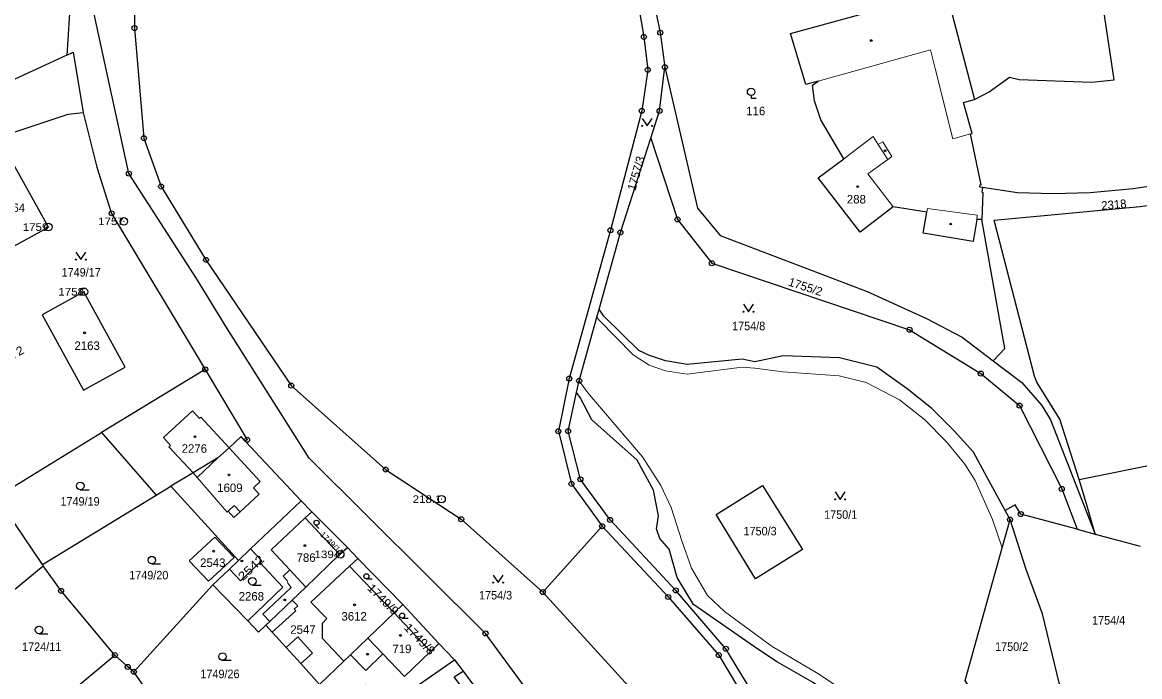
# Model space of a CAD drawing. Extents: x -679733 to -673243, y -1075091 to -1066557.
# Drawn here: x -676657.5 to -676434.7, y -1072048.7 to -1071918.1 of the extents above; entities that cross this region are included whole.
import ezdxf
from ezdxf.enums import TextEntityAlignment as Align

# ---------------------------------------------------------------- set-up
doc = ezdxf.new("R2010")
doc.units = 0
doc.header["$LTSCALE"] = 0.68
for name, color, linetype, lineweight in [('1', 7, 'Continuous', 25), ('3', 7, 'Continuous', 25), ('4', 7, 'Continuous', 13), ('5', 7, 'Continuous', 25), ('8', 7, 'Continuous', 25)]:
    doc.layers.add(name, color=color, linetype=linetype, lineweight=lineweight)
doc.layers.add('2', color=7, linetype='Continuous')

msp = doc.modelspace()

# ---------------------------------------------------------------- linework, layer by layer
at = {"layer": '1'}
for p, q in [((-676648.66, -1071924.71), (-676677.79, -1071938.14)), ((-676662.66, -1072012.82), (-676641.72, -1072000.02)), ((-676446.81, -1072009.39), (-676405.43, -1072000.99)), ((-676630.86, -1072012.51), (-676627.91, -1072010.71)), ((-676653.53, -1072026.32), (-676630.86, -1072012.51)), ((-676601.93, -1072013.64), (-676612.02, -1072023.23)), ((-676541.89, -1072018.69), (-676553.76, -1072031.84)), ((-676447.16, -1072019.31), (-676443.59, -1072020.28)), ((-676443.59, -1072020.28), (-676434.63, -1072022.7)), ((-676614.43, -1072025.51), (-676612.02, -1072023.23)), ((-676594.3, -1072024.34), (-676592.72, -1072022.97)), ((-676614.43, -1072025.51), (-676616.25, -1072027.25)), ((-676619.53, -1072030.36), (-676612.59, -1072037.56)), ((-676581.66, -1072034.34), (-676583.38, -1072036)), ((-676664.27, -1072065.35), (-676639.08, -1072044.43))]:
    msp.add_line(p, q, dxfattribs=at)
for points in [[(-676651.25, -1071520.53), (-676649.67, -1071525.28), (-676636.33, -1071567.59), (-676632.67, -1071580.29), (-676618.91, -1071616.92), (-676601.45, -1071672.26), (-676590.27, -1071707.98), (-676587.53, -1071724.18), (-676588.53, -1071766.09), (-676588.57, -1071776.49), (-676583.64, -1071788.99), (-676568.69, -1071809.98), (-676555.21, -1071828.53), (-676552.27, -1071835.54), (-676544.88, -1071865.16), (-676535.44, -1071910.25), (-676533.59, -1071921.04), (-676532.8, -1071927.61), (-676534.01, -1071935.8), (-676540.25, -1071959.64), (-676548.46, -1071989.23), (-676550.64, -1071999.75), (-676548.02, -1072010.25), (-676541.89, -1072018.69)], [(-676536.59, -1072122.5), (-676533.92, -1072098.22), (-676545.12, -1072067.43), (-676565.16, -1072040.09), (-676600.33, -1072005.09), (-676616.66, -1071979.22), (-676622.81, -1071969.28), (-676636.28, -1071948.34), (-676643.38, -1071915.55), (-676643.27, -1071912.66), (-676641.57, -1071878.93), (-676640.51, -1071869.39), (-676644.08, -1071858.21), (-676648.12, -1071848.64), (-676652.14, -1071843.11), (-676662.12, -1071830.1), (-676667.77, -1071822.29), (-676671.63, -1071816.16), (-676675.84, -1071808.46), (-676684.53, -1071784.41), (-676687.42, -1071776.51), (-676692.78, -1071762.77), (-676693.21, -1071759.8)], [(-676693.21, -1071759.8), (-676682.45, -1071780.64), (-676664.29, -1071814.93), (-676647.47, -1071846.25), (-676640.24, -1071862.09), (-676636.02, -1071877.65), (-676635.05, -1071901.27), (-676635.17, -1071919.29), (-676633.29, -1071941.26), (-676629.86, -1071950.91), (-676620.91, -1071965.54), (-676603.92, -1071990.64), (-676585.08, -1072007.38), (-676570.01, -1072017.31), (-676553.76, -1072031.84)], [(-676646.18, -1071888.84), (-676647.91, -1071913.21), (-676648.66, -1071924.71)], [(-676467.67, -1071933.53), (-676464.71, -1071932.01), (-676460.66, -1071929.1), (-676458.76, -1071929.54), (-676444.35, -1071930.11), (-676439.77, -1071929.59), (-676443.23, -1071906.44), (-676443.65, -1071901.85), (-676443.9, -1071898.2)], [(-676532.57, -1071909.38), (-676530.33, -1071920.2), (-676529.39, -1071927.09)], [(-676466.17, -1071957.49), (-676467.17, -1071957.46), (-676467.89, -1071961.85), (-676477.86, -1071960.21), (-676477.17, -1071956.02), (-676483.88, -1071954.95), (-676490.43, -1071960.03), (-676498.83, -1071949.2), (-676493.74, -1071945.38), (-676498.32, -1071937.6), (-676499.59, -1071933.8), (-676499.97, -1071930.7), (-676498.81, -1071929.86), (-676501.29, -1071930.55), (-676504.35, -1071920.4), (-676478.53, -1071913.23), (-676478.08, -1071915.44), (-676472.8, -1071914.02), (-676467.67, -1071933.53)], [(-676648.66, -1071924.71), (-676647.38, -1071924.12), (-676645.42, -1071936.13)], [(-676532.21, -1071941.28), (-676530.45, -1071935.82), (-676529.39, -1071927.09)], [(-676529.39, -1071927.09), (-676522.91, -1071955.2), (-676518.38, -1071960.68), (-676489.07, -1071971.86), (-676477.2, -1071977.24), (-676470.13, -1071980.98), (-676463.93, -1071985.69)], [(-676466.06, -1071951.13), (-676466.62, -1071951.02), (-676466.55, -1071950.53), (-676466.32, -1071950.54), (-676468.43, -1071940.39), (-676468.09, -1071940.3), (-676469.85, -1071934.11), (-676467.67, -1071933.53)], [(-676677.79, -1071938.14), (-676683.04, -1071941.07), (-676688.79, -1071944.72), (-676697.74, -1071951.6), (-676686.87, -1071955.62), (-676682.71, -1071949.46), (-676676.66, -1071945.82), (-676648.39, -1071936.48), (-676645.42, -1071936.13)], [(-676645.42, -1071936.13), (-676642.71, -1071947.04), (-676640.27, -1071954.61), (-676639.72, -1071956.26), (-676621.07, -1071987.4)], [(-676542.52, -1071975.41), (-676538.26, -1071960.09), (-676532.21, -1071941.28)], [(-676532.21, -1071941.28), (-676526.88, -1071957.48), (-676520.03, -1071966.22), (-676480.59, -1071979.49), (-676466.4, -1071988.24), (-676458.66, -1071994.62), (-676450.24, -1072011.26), (-676447.16, -1072019.31)], [(-676407.29, -1071945.44), (-676417.02, -1071948.01), (-676425.37, -1071949.72), (-676430.22, -1071950.53), (-676436.03, -1071951.34), (-676444.6, -1071952.15), (-676451.96, -1071952.38), (-676459.08, -1071952.16), (-676466.06, -1071951.13)], [(-676446.81, -1072009.39), (-676450.6, -1071997.32), (-676455.21, -1071989.93), (-676455.68, -1071988.73), (-676463.71, -1071957.6), (-676434.64, -1071954.92), (-676421.63, -1071953.01), (-676421.61, -1071953.11), (-676406.22, -1071948.58), (-676402.7, -1071947.59), (-676390.08, -1071946.22)], [(-676466.06, -1071951.13), (-676466.19, -1071952.06), (-676466, -1071952.07), (-676466.17, -1071957.49)], [(-676463.93, -1071985.69), (-676461.59, -1071983.26), (-676466.17, -1071957.49)], [(-676547, -1071992.02), (-676546.49, -1071989.69), (-676542.97, -1071977.01), (-676542.52, -1071975.41)], [(-676461.53, -1072015.53), (-676465.21, -1072008.84), (-676467.86, -1072003.89), (-676471.68, -1071999.63), (-676476.13, -1071995.23), (-676481.11, -1071991.28), (-676487.12, -1071986.98), (-676494.59, -1071985.06), (-676505.82, -1071984.72), (-676511.48, -1071985.89), (-676513.98, -1071985.36), (-676524.96, -1071986.4), (-676529.28, -1071985.72), (-676532.48, -1071984.66), (-676534.57, -1071983.66), (-676541.58, -1071976.77), (-676542.52, -1071975.41)], [(-676463.93, -1071985.69), (-676458.21, -1071990.03), (-676454.22, -1071994.63), (-676452.5, -1071997.49), (-676443.59, -1072020.28)], [(-676621.07, -1071987.4), (-676641.72, -1072000.02), (-676630.86, -1072012.51)], [(-676621.07, -1071987.4), (-676612.71, -1072001.45), (-676613.1, -1072001.69), (-676601.93, -1072013.64), (-676599.8, -1072015.8), (-676592.72, -1072022.97), (-676590.64, -1072025.11), (-676581.66, -1072034.34), (-676574.45, -1072042.12), (-676571.33, -1072045.34), (-676569.62, -1072047.62), (-676562.71, -1072057.02)], [(-676500.11, -1072113.78), (-676499.62, -1072097.03), (-676500.1, -1072084.73), (-676503.89, -1072069.84), (-676509.41, -1072056.04), (-676517.24, -1072043.14), (-676527.22, -1072031.51), (-676540.33, -1072017.45), (-676546.23, -1072009.34), (-676548.7, -1071999.72), (-676547, -1071992.02)], [(-676441.35, -1072078.63), (-676446.64, -1072079.9), (-676450.67, -1072079.56), (-676457.64, -1072077.18), (-676462.64, -1072074.44), (-676465.22, -1072072.72), (-676468.93, -1072069.87), (-676483.47, -1072060.58), (-676485.65, -1072059.67), (-676489.93, -1072056.7), (-676499.98, -1072049.83), (-676506.93, -1072045.81), (-676510.86, -1072043.21), (-676523.71, -1072034.33), (-676526.92, -1072028.9), (-676528.54, -1072023.25), (-676530.38, -1072021.18), (-676531.08, -1072019.23), (-676530.64, -1072016.6), (-676531.69, -1072011.51), (-676534.93, -1072005.54), (-676543.94, -1071997.47), (-676546.26, -1071993.04), (-676547, -1071992.02)], [(-676613.1, -1072001.69), (-676613.92, -1072000.81), (-676616.28, -1072003.03), (-676618.57, -1072005.02), (-676623.47, -1072008.01), (-676627.91, -1072010.71), (-676614.43, -1072025.51)], [(-676653.53, -1072026.32), (-676662.66, -1072012.82), (-676665.05, -1072008.87)], [(-676443.59, -1072020.28), (-676445.29, -1072014.21), (-676446.81, -1072009.39)], [(-676448.65, -1072056.78), (-676451.96, -1072055.88), (-676468.3, -1072051.44), (-676469.48, -1072049.46), (-676462.13, -1072022.99), (-676460.57, -1072017.38), (-676461.53, -1072015.53)], [(-676447.16, -1072019.31), (-676458.43, -1072016.27), (-676459.55, -1072014.43), (-676461.53, -1072015.53)], [(-676594.3, -1072024.34), (-676601.12, -1072017.04), (-676599.8, -1072015.8)], [(-676448.65, -1072056.78), (-676448.76, -1072056.48), (-676450.74, -1072049.94), (-676454.08, -1072036.2), (-676457.34, -1072027.31), (-676460.57, -1072017.38)], [(-676541.89, -1072018.69), (-676528.74, -1072032.82), (-676518.66, -1072044.42), (-676511.2, -1072056.95), (-676505.9, -1072070.52), (-676502.09, -1072084.93), (-676501.62, -1072096.94), (-676502.1, -1072114.34), (-676501.22, -1072116.73), (-676500.34, -1072121.98), (-676502.88, -1072124.51), (-676503.32, -1072130.04), (-676504.31, -1072153.57), (-676506.28, -1072192.84), (-676507.47, -1072212.67), (-676507.15, -1072233.46), (-676502.3, -1072253.2), (-676493.52, -1072270.33), (-676481.52, -1072286.7), (-676450.04, -1072327.35), (-676442.42, -1072339.58), (-676438, -1072351.9), (-676440.64, -1072365.35), (-676434.8, -1072359.89)], [(-676612.02, -1072023.23), (-676609.77, -1072025.59), (-676610.16, -1072025.96)], [(-676608.96, -1072038.42), (-676608.2, -1072037.7), (-676603.74, -1072033.46), (-676601, -1072030.84), (-676594.3, -1072024.34)], [(-676678.73, -1072047.51), (-676653.4, -1072026.6), (-676653.53, -1072026.32)], [(-676639.08, -1072044.43), (-676649.81, -1072031.6), (-676653.4, -1072026.6)], [(-676616.25, -1072027.25), (-676614.01, -1072029.61), (-676610.16, -1072025.96)], [(-676610.16, -1072025.96), (-676605.61, -1072030.88), (-676612.59, -1072037.56)], [(-676593.41, -1072045.63), (-676597.68, -1072041.1), (-676597.66, -1072038.02), (-676596.78, -1072037.12), (-676599.97, -1072033.85), (-676592.32, -1072026.68)], [(-676590.64, -1072025.11), (-676592.32, -1072026.68), (-676583.38, -1072036)], [(-676635.3, -1072047.75), (-676619.53, -1072030.36), (-676616.25, -1072027.25)], [(-676553.76, -1072031.84), (-676533.17, -1072054.44), (-676527.24, -1072064.82), (-676522.81, -1072075.75), (-676520.39, -1072086.47), (-676519.96, -1072097.33), (-676521.47, -1072117.29)], [(-676612.59, -1072037.56), (-676610.42, -1072039.82), (-676608.96, -1072038.42)], [(-676583.38, -1072036), (-676588.63, -1072041.05), (-676592.06, -1072044.34), (-676593.41, -1072045.63), (-676598.25, -1072050.28)], [(-676574.45, -1072042.12), (-676576.12, -1072043.71), (-676583.38, -1072036)], [(-676598.25, -1072050.28), (-676602.01, -1072046.12), (-676604.94, -1072042.87), (-676607.7, -1072039.81), (-676608.96, -1072038.42)], [(-676635.3, -1072047.75), (-676636.51, -1072046.77), (-676639.08, -1072044.43)], [(-676594.16, -1072056.99), (-676590.16, -1072054.55), (-676591.83, -1072052.1), (-676589.07, -1072050.2), (-676584.45, -1072054.47), (-676571.33, -1072045.34)], [(-676627.53, -1072061.09), (-676630.33, -1072054.92), (-676635.3, -1072047.75)], [(-676564.44, -1072058.21), (-676571.43, -1072048.77), (-676569.62, -1072047.62)]]:
    msp.add_lwpolyline(points, dxfattribs=at)
for points in [[(-676660.7, -1071963.64), (-676652.34, -1071959), (-676660.63, -1071944.05), (-676668.99, -1071948.69)], [(-676637, -1071986.97), (-676645.24, -1071971.91), (-676653.59, -1071976.48), (-676645.35, -1071991.54)], [(-676519.2, -1072016.38), (-676509.92, -1072010.56), (-676501.93, -1072023.32), (-676511.33, -1072029.17)], [(-676619.12, -1072020.89), (-676624.25, -1072025.62), (-676620.4, -1072029.67), (-676615.28, -1072024.94)]]:
    msp.add_lwpolyline(points, close=True, dxfattribs=at)
at = {"layer": '3'}
for p, q in [((-676645.983, -1072011.41), (-676644.233, -1072011.41)), ((-676599.207, -1072018.353), (-676598.378, -1072019.182)), ((-676631.703, -1072026.21), (-676629.953, -1072026.21)), ((-676611.663, -1072030.44), (-676609.913, -1072030.44)), ((-676588.925, -1072029.19), (-676587.753, -1072029.19)), ((-676581.795, -1072037.03), (-676580.623, -1072037.03)), ((-676654.193, -1072040.15), (-676652.443, -1072040.15)), ((-676617.623, -1072045.46), (-676615.873, -1072045.46))]:
    msp.add_line(p, q, dxfattribs=at)
for points in [[(-676512.2, -1071932.762), (-676512.2, -1071933.26), (-676511.199, -1071933.26)], [(-676533.95, -1071937.319), (-676532.95, -1071938.82), (-676531.95, -1071937.319)], [(-676646.89, -1071963.979), (-676645.89, -1071965.48), (-676644.89, -1071963.979)], [(-676513.73, -1071974.409), (-676512.73, -1071975.91), (-676511.73, -1071974.409)], [(-676495.44, -1072011.859), (-676494.44, -1072013.36), (-676493.44, -1072011.859)], [(-676563.66, -1072028.449), (-676562.66, -1072029.95), (-676561.66, -1072028.449)]]:
    msp.add_lwpolyline(points, dxfattribs=at)
for centre, radius in [((-676512.1993, -1071932.0109), 0.75), ((-676533.95, -1071938.8195), 0.1), ((-676531.95, -1071938.8195), 0.1), ((-676646.89, -1071965.4795), 0.1), ((-676644.89, -1071965.4795), 0.1), ((-676513.73, -1071975.9095), 0.1), ((-676511.73, -1071975.9095), 0.1), ((-676645.9829, -1072010.6598), 0.75), ((-676495.44, -1072013.3595), 0.1), ((-676493.44, -1072013.3595), 0.1), ((-676598.8512, -1072017.998), 0.5025), ((-676631.7029, -1072025.4598), 0.75), ((-676611.6629, -1072029.6898), 0.75), ((-676588.9252, -1072028.6874), 0.5025), ((-676563.66, -1072029.9495), 0.1), ((-676561.66, -1072029.9495), 0.1), ((-676581.7952, -1072036.5274), 0.5025), ((-676654.1929, -1072039.3998), 0.75), ((-676617.6229, -1072044.7098), 0.75)]:
    msp.add_circle(centre, radius, dxfattribs=at)
at = {"layer": '4'}
for p, q in [((-676498.81, -1071929.86), (-676476.43, -1071923.65)), ((-676476.43, -1071923.65), (-676475.5, -1071927.33)), ((-676475.5, -1071927.33), (-676471.99, -1071941.39)), ((-676493.74, -1071945.38), (-676487.84, -1071940.91)), ((-676487.84, -1071940.91), (-676486.88, -1071942.52)), ((-676486.88, -1071942.52), (-676485.95, -1071941.99)), ((-676485.95, -1071941.99), (-676484.12, -1071944.94)), ((-676471.99, -1071941.39), (-676468.43, -1071940.39)), ((-676484.93, -1071945.51), (-676486.88, -1071942.52)), ((-676488.94, -1071948.35), (-676484.93, -1071945.51)), ((-676484.12, -1071944.94), (-676484.93, -1071945.51)), ((-676488.94, -1071948.35), (-676483.88, -1071954.95)), ((-676477.05, -1071955.27), (-676477.17, -1071956.02)), ((-676467.14, -1071956.61), (-676477.05, -1071955.27)), ((-676467.17, -1071957.46), (-676467.14, -1071956.61)), ((-676542.97, -1071977.01), (-676542.57, -1071977.52)), ((-676542.57, -1071977.52), (-676535.71, -1071984.51)), ((-676535.71, -1071984.51), (-676532.51, -1071986.56)), ((-676532.51, -1071986.56), (-676529.3, -1071987.71)), ((-676529.3, -1071987.71), (-676524.98, -1071988.32)), ((-676524.98, -1071988.32), (-676514, -1071986.96)), ((-676514, -1071986.96), (-676511.49, -1071987.17)), ((-676511.49, -1071987.17), (-676505.86, -1071987.92)), ((-676505.86, -1071987.92), (-676494.64, -1071988.71)), ((-676494.64, -1071988.71), (-676489.27, -1071990.04)), ((-676546.49, -1071989.69), (-676544.75, -1071992.06)), ((-676489.27, -1071990.04), (-676482.63, -1071993.45)), ((-676544.75, -1071992.06), (-676533.84, -1072004.83)), ((-676482.63, -1071993.45), (-676477.65, -1071997.39)), ((-676629.4, -1072001.02), (-676623.61, -1071995.66)), ((-676623.61, -1071995.66), (-676622.21, -1071997.18)), ((-676622.21, -1071997.18), (-676621.93, -1071996.93)), ((-676621.93, -1071996.93), (-676616.28, -1072003.03)), ((-676477.65, -1071997.39), (-676473.22, -1072001.83)), ((-676627.98, -1072002.56), (-676629.4, -1072001.02)), ((-676473.22, -1072001.83), (-676469.56, -1072006.31)), ((-676628.3, -1072002.85), (-676627.98, -1072002.56)), ((-676623.47, -1072008.01), (-676628.3, -1072002.85)), ((-676610.11, -1072009.79), (-676616.28, -1072003.03)), ((-676622.65, -1072008.95), (-676618.57, -1072005.02)), ((-676533.84, -1072004.83), (-676530.21, -1072010.54)), ((-676469.56, -1072006.31), (-676467.55, -1072009.57)), ((-676623.47, -1072008.01), (-676622.65, -1072008.95)), ((-676622.65, -1072008.95), (-676616.67, -1072015.87)), ((-676611.44, -1072011.01), (-676610.11, -1072009.79)), ((-676610.29, -1072012.33), (-676611.44, -1072011.01)), ((-676530.21, -1072010.54), (-676528.16, -1072014.98)), ((-676467.55, -1072009.57), (-676464.05, -1072017.36)), ((-676614.11, -1072015.84), (-676610.29, -1072012.33)), ((-676615.26, -1072014.59), (-676616.46, -1072015.69)), ((-676614.11, -1072015.84), (-676615.26, -1072014.59)), ((-676528.16, -1072014.98), (-676526.01, -1072021.6)), ((-676616.67, -1072015.87), (-676616.46, -1072015.69)), ((-676616.46, -1072015.69), (-676615.35, -1072016.97)), ((-676615.35, -1072016.97), (-676614.11, -1072015.84)), ((-676601.12, -1072017.04), (-676607.93, -1072023.42)), ((-676464.05, -1072017.36), (-676462.13, -1072022.99)), ((-676526.01, -1072021.6), (-676524.12, -1072027.07)), ((-676607.93, -1072023.42), (-676604.19, -1072027.41)), ((-676604.19, -1072027.41), (-676605.54, -1072028.68)), ((-676605.54, -1072028.68), (-676604.75, -1072029.52)), ((-676604.19, -1072027.41), (-676601, -1072030.84)), ((-676524.12, -1072027.07), (-676520.9, -1072032.49)), ((-676604.75, -1072029.52), (-676604.59, -1072030.05)), ((-676604.59, -1072030.05), (-676603.91, -1072030.92)), ((-676520.9, -1072032.49), (-676517.52, -1072035.74)), ((-676607.7, -1072039.81), (-676603.02, -1072035.58)), ((-676602.62, -1072034.61), (-676603.74, -1072033.46)), ((-676603.32, -1072035.25), (-676602.62, -1072034.61)), ((-676603.02, -1072035.58), (-676603.32, -1072035.25)), ((-676517.52, -1072035.74), (-676507.97, -1072042.7)), ((-676604.94, -1072042.87), (-676602.62, -1072040.77)), ((-676602.62, -1072040.77), (-676599.68, -1072044.01)), ((-676585.62, -1072044.19), (-676588.63, -1072041.05)), ((-676599.68, -1072044.01), (-676602.01, -1072046.12)), ((-676592.06, -1072044.34), (-676589.05, -1072047.48)), ((-676589.05, -1072047.48), (-676585.62, -1072044.19)), ((-676585.62, -1072044.19), (-676581.33, -1072048.67)), ((-676581.33, -1072048.67), (-676576.12, -1072043.71)), ((-676507.97, -1072042.7), (-676498.88, -1072048.06)), ((-676498.88, -1072048.06), (-676490.19, -1072053.83))]:
    msp.add_line(p, q, dxfattribs=at)
msp.add_lwpolyline([(-676603.91, -1072030.92), (-676609.58, -1072036.23), (-676608.2, -1072037.7)], dxfattribs=at)
at = {"layer": '5'}
for centre in [(-676488.2368, -1071921.7892), (-676485.4768, -1071943.7592), (-676490.9468, -1071950.9292), (-676472.3968, -1071958.3892), (-676645.1368, -1071980.1092), (-676623.0968, -1072000.8492), (-676616.3268, -1072008.4592), (-676619.3768, -1072023.6792), (-676601.1768, -1072022.5592), (-676613.7568, -1072025.6292), (-676605.2068, -1072033.3992), (-676591.3068, -1072034.3792), (-676582.1268, -1072040.4892), (-676588.7068, -1072044.2392)]:
    msp.add_circle(centre, 0.175, dxfattribs=at)
at = {"layer": '8'}
for centre, radius in [((-676635.17, -1071919.2899), 0.5), ((-676635.17, -1071919.2899), 0.0303), ((-676530.33, -1071920.1999), 0.5), ((-676533.59, -1071921.0399), 0.5), ((-676533.59, -1071921.0399), 0.0303), ((-676530.33, -1071920.1999), 0.0303), ((-676532.8, -1071927.6099), 0.5), ((-676532.8, -1071927.6099), 0.0303), ((-676529.39, -1071927.0899), 0.5), ((-676529.39, -1071927.0899), 0.0303), ((-676534.01, -1071935.7999), 0.5), ((-676530.45, -1071935.8199), 0.5), ((-676534.01, -1071935.7999), 0.0303), ((-676530.45, -1071935.8199), 0.0303), ((-676633.29, -1071941.2599), 0.5), ((-676633.29, -1071941.2599), 0.0303), ((-676636.28, -1071948.3399), 0.5), ((-676636.28, -1071948.3399), 0.0303), ((-676629.86, -1071950.9099), 0.5), ((-676629.86, -1071950.9099), 0.0303), ((-676639.72, -1071956.2599), 0.5), ((-676639.72, -1071956.2599), 0.0303), ((-676637.29, -1071957.8598), 0.75), ((-676526.88, -1071957.4799), 0.5), ((-676526.88, -1071957.4799), 0.0303), ((-676652.34, -1071958.9998), 0.75), ((-676652.34, -1071958.9998), 0.03), ((-676637.29, -1071957.8598), 0.03), ((-676540.25, -1071959.6399), 0.5), ((-676540.25, -1071959.6399), 0.0303), ((-676538.26, -1071960.0899), 0.5), ((-676538.26, -1071960.0899), 0.0303), ((-676620.91, -1071965.5399), 0.5), ((-676620.91, -1071965.5399), 0.0303), ((-676520.03, -1071966.2199), 0.5), ((-676520.03, -1071966.2199), 0.0303), ((-676645.24, -1071971.9098), 0.75), ((-676645.24, -1071971.9098), 0.03), ((-676480.59, -1071979.4899), 0.5), ((-676480.59, -1071979.4899), 0.0303), ((-676621.07, -1071987.3999), 0.5), ((-676621.07, -1071987.3999), 0.0303), ((-676548.46, -1071989.2299), 0.5), ((-676466.4, -1071988.2399), 0.5), ((-676466.4, -1071988.2399), 0.0303), ((-676603.92, -1071990.6399), 0.5), ((-676603.92, -1071990.6399), 0.0303), ((-676548.46, -1071989.2299), 0.0303), ((-676546.49, -1071989.6899), 0.5), ((-676546.49, -1071989.6899), 0.0303), ((-676458.66, -1071994.6199), 0.5), ((-676458.66, -1071994.6199), 0.0303), ((-676550.64, -1071999.7499), 0.5), ((-676550.64, -1071999.7499), 0.0303), ((-676548.7, -1071999.7199), 0.5), ((-676548.7, -1071999.7199), 0.0303), ((-676612.71, -1072001.4499), 0.5), ((-676612.71, -1072001.4499), 0.0303), ((-676585.08, -1072007.3799), 0.5), ((-676585.08, -1072007.3799), 0.0303), ((-676546.23, -1072009.3399), 0.5), ((-676548.02, -1072010.2499), 0.5), ((-676548.02, -1072010.2499), 0.0303), ((-676546.23, -1072009.3399), 0.0303), ((-676450.24, -1072011.2599), 0.5), ((-676573.93, -1072013.2998), 0.75), ((-676573.93, -1072013.2998), 0.03), ((-676450.24, -1072011.2599), 0.0303), ((-676570.01, -1072017.3099), 0.5), ((-676570.01, -1072017.3099), 0.0303), ((-676540.33, -1072017.4499), 0.5), ((-676540.33, -1072017.4499), 0.0303), ((-676460.57, -1072017.3799), 0.5), ((-676460.57, -1072017.3799), 0.0303), ((-676458.43, -1072016.2699), 0.5), ((-676458.43, -1072016.2699), 0.0303), ((-676541.89, -1072018.6899), 0.5), ((-676541.89, -1072018.6899), 0.0303), ((-676594.14, -1072024.3098), 0.75), ((-676594.14, -1072024.3098), 0.03), ((-676649.81, -1072031.5999), 0.5), ((-676527.22, -1072031.5099), 0.5), ((-676649.81, -1072031.5999), 0.0303), ((-676553.76, -1072031.8399), 0.5), ((-676553.76, -1072031.8399), 0.0303), ((-676528.74, -1072032.8199), 0.5), ((-676528.74, -1072032.8199), 0.0303), ((-676527.22, -1072031.5099), 0.0303), ((-676565.16, -1072040.0899), 0.5), ((-676565.16, -1072040.0899), 0.0303), ((-676639.08, -1072044.4299), 0.5), ((-676639.08, -1072044.4299), 0.0303), ((-676518.66, -1072044.4199), 0.5), ((-676518.66, -1072044.4199), 0.0303), ((-676517.24, -1072043.1399), 0.5), ((-676517.24, -1072043.1399), 0.0303), ((-676636.51, -1072046.7699), 0.5), ((-676636.51, -1072046.7699), 0.0303), ((-676635.3, -1072047.7499), 0.5), ((-676635.3, -1072047.7499), 0.0303)]:
    msp.add_circle(centre, radius, dxfattribs=at)

# ---------------------------------------------------------------- texts
at = {"layer": '2'}
for s, p in [('116', (-676513.17, -1071936.68)), ('288', (-676493.1, -1071954.29)), ('2164', (-676662.04, -1071955.999)), ('2163', (-676647.14, -1071983.519)), ('2276', (-676625.76, -1072004.04)), ('1609', (-676618.67, -1072011.88)), ('786', (-676602.84, -1072025.81)), ('2543', (-676622.08, -1072026.82)), ('2268', (-676614.39, -1072033.529)), ('3612', (-676593.9, -1072037.529)), ('2547', (-676604.1, -1072040.17)), ('719', (-676583.73, -1072044.019))]:
    msp.add_text(s, height=1.7, dxfattribs=at).set_placement(p)
for s, rotation, p in [('1757/3', 74, (-676535.282, -1071951.834)), ('2318', 5, (-676442.305, -1071955.576)), ('1755/2', 342, (-676504.922, -1071970.638))]:
    msp.add_text(s, height=1.7, rotation=rotation, dxfattribs=at).set_placement(p)
at = {"layer": '2', "width": 0.95}
for s, p in [('1749/17', (-676649.7, -1071968.87)), ('1754/8', (-676515.99, -1071979.58)), ('1749/19', (-676649.93, -1072014.59)), ('1750/1', (-676497.64, -1072017.22)), ('1749/20', (-676636.22, -1072029.31)), ('1754/3', (-676566.46, -1072033.31)), ('1754/4', (-676444.2, -1072038.32)), ('1724/11', (-676657.59, -1072043.6)), ('1750/2', (-676463.54, -1072043.57)), ('1749/26', (-676622.03, -1072049.019))]:
    msp.add_text(s, height=1.7, dxfattribs=at).set_placement(p)
at = {"layer": '2'}
for s, height, rotation, width, p in [('2172', 1.7, 29, 1.1, (-676661.867, -1071986.783)), ('1749/11', 1.14, 315, 1.05, (-676598.273, -1072020.463)), ('2542', 1.7, 43, 1.2, (-676613.56, -1072029.691)), ('1749/9', 1.7, 315, 1.1, (-676588.871, -1072031.191)), ('1749/8', 1.7, 314, 1.1, (-676581.551, -1072039.06))]:
    msp.add_text(s, height=height, rotation=rotation, dxfattribs=dict(at, width=width)).set_placement(p)
at = {"layer": '2', "width": 0.95}
msp.add_text('1750/3', height=1.7, dxfattribs=at).set_placement((-676510.409, -1072020.529), align=Align.CENTER)
at = {"layer": '8', "width": 1.15}
for s, p in [('1757', (-676637.289, -1071958.61)), ('1759', (-676652.339, -1071959.75)), ('1758', (-676645.239, -1071972.659)), ('218.1', (-676573.929, -1072014.05)), ('1394', (-676594.139, -1072025.06))]:
    msp.add_text(s, height=1.5, dxfattribs=at).set_placement(p, align=Align.RIGHT)

doc.saveas('drawing.dxf')
